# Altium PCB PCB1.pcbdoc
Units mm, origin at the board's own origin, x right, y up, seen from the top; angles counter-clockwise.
Board outline 74 x 38.88 mm, 2 copper layers (Top Layer, Bottom Layer); 38 components, 29 nets, 149 pads, 0 vias.
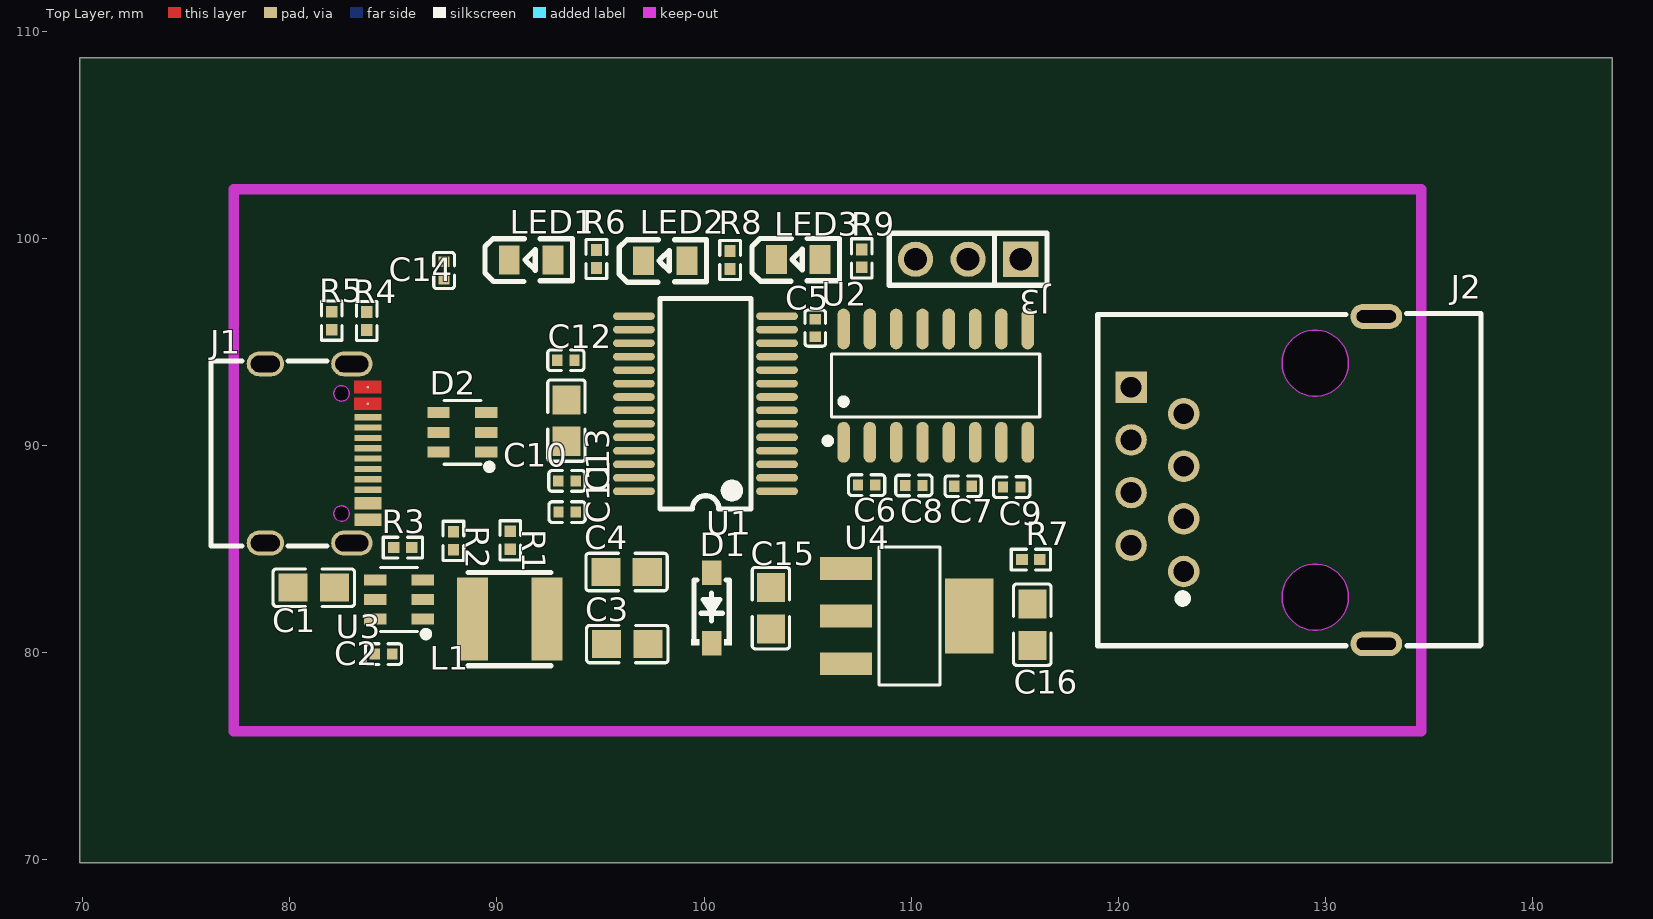
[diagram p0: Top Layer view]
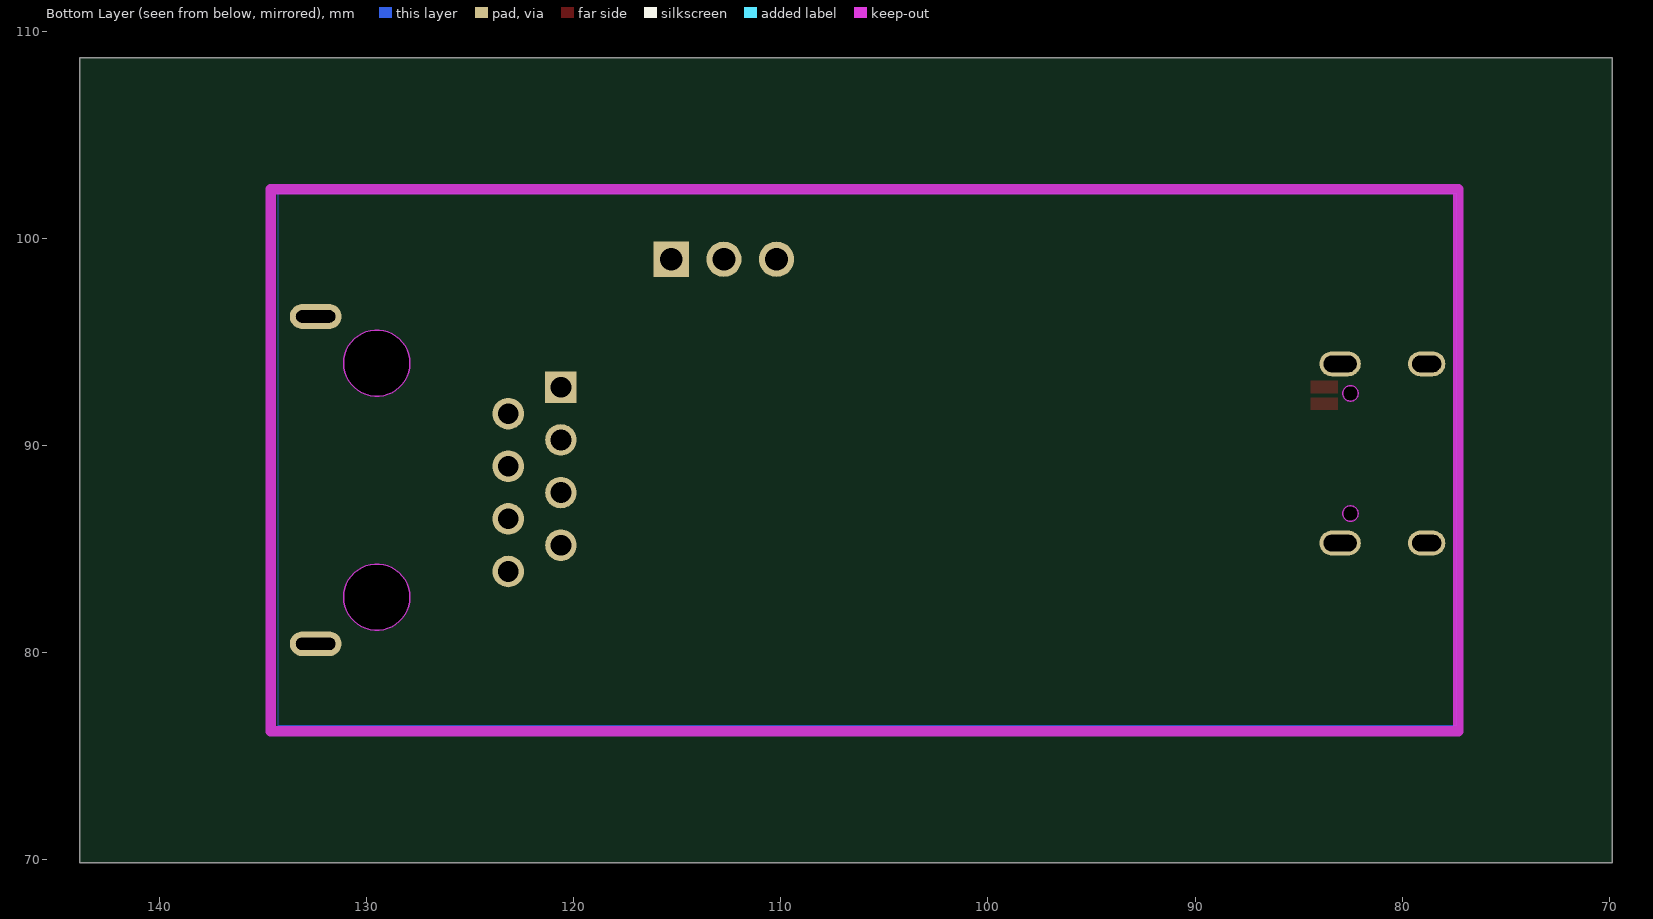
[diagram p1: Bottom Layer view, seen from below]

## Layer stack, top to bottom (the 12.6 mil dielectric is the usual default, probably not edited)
Top Layer: signal copper (thickness not stored)
Dielectric: dielectric 0.32, FR-4, Dk 4.8
Bottom Layer: signal copper (thickness not stored)

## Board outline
143.855,69.85 69.85,69.85 69.85,108.735 143.855,108.735

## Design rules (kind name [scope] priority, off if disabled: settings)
BoardOutlineClearance copperThickness1oz [All] p0: genericclearance=0.254 ignorepadtopadclearanceinfootprint=FALSE except(0: Arc-SplitContinuation Track-SplitContinuation SMDPad-SplitContinuation THPad-SplitContinuation Via-SplitContinuation Fill-SplitContinuation Poly-SplitContinuation Region-SplitContinuation Text-SplitContinuation; 0.152: SMDPad-CutoutEdge THPad-CutoutEdge Via-CutoutEdge Fill-CutoutEdge Region-CutoutEdge; 0.3: Track-OutlineEdge SMDPad-OutlineEdge THPad-OutlineEdge Via-OutlineEdge Fill-OutlineEdge Region-OutlineEdge Poly-OutlineEdge Text-OutlineEdge Track-CutoutEdge)
BoardOutlineClearance copperThickness2oz [All] p0: genericclearance=0.254 ignorepadtopadclearanceinfootprint=FALSE except(0: Arc-SplitContinuation Track-SplitContinuation SMDPad-SplitContinuation THPad-SplitContinuation Via-SplitContinuation Fill-SplitContinuation Poly-SplitContinuation Region-SplitContinuation Text-SplitContinuation; 0.152: SMDPad-CutoutEdge THPad-CutoutEdge Via-CutoutEdge Fill-CutoutEdge Region-CutoutEdge; 0.3: Track-OutlineEdge SMDPad-OutlineEdge THPad-OutlineEdge Via-OutlineEdge Fill-OutlineEdge Region-OutlineEdge Poly-OutlineEdge Text-OutlineEdge Track-CutoutEdge)
Clearance copperThickness1oz [(InNet('GND') OR InNet('VUSB') OR InNet('VBOOST') OR InNet('$1N3108') OR InNet('$1N3104') OR InNet('$1N3119') OR InNet('$1N3114') OR InNet('$1N3125') OR InNet('$1N3129') OR InNet('V12_OUT') OR InNet('UD+') OR InNet('UD-') OR InNet('$1N2860') OR InNet('$1N4089') OR InNet('TXLED') OR InNet('$1N4091') OR InNet('RXLED') OR InNet('$1N4093') OR InNet('$1N2875') OR InNet('$1N2847') OR InNet('$1N3909') OR InNet('$1N3913') OR InNet('$1N3570') OR InNet('RS232_RX') OR InNet('RS232_TX') OR InNet('UART_TX') OR InNet('UART_RX') OR InNet('$1N3345') OR InNet('V3V3'))] p1: gap=0.178 ignorepadtopadclearanceinfootprint=FALSE except(0.102: Track-Track; 0.152: Track-SMDPad SMDPad-SMDPad Track-THPad SMDPad-THPad THPad-THPad Track-Via SMDPad-Via THPad-Via Via-Via Track-Fill SMDPad-Fill THPad-Fill Via-Fill Fill-Fill SMDPad-Region THPad-Region Via-Region Fill-Region Region-Region Track-Poly SMDPad-Poly THPad-Poly Via-Poly Fill-Poly Poly-Poly Track-Text SMDPad-Text THPad-Text Via-Text Fill-Text Region-Text Poly-Text Text-Text; 0.175: Track-Hole SMDPad-Hole THPad-Hole Via-Hole Fill-Hole Region-Hole Poly-Hole Text-Hole Sheet-Hole; 0.3: Track-Region Region-Poly Track-Sheet SMDPad-Sheet THPad-Sheet Via-Sheet Fill-Sheet Region-Sheet Poly-Sheet Text-Sheet)
Clearance copperThickness2oz [All] p1: gap=0.178 ignorepadtopadclearanceinfootprint=FALSE except(0.152: Track-SMDPad SMDPad-SMDPad Track-THPad SMDPad-THPad THPad-THPad Track-Via SMDPad-Via THPad-Via Via-Via Track-Fill SMDPad-Fill THPad-Fill Via-Fill Fill-Fill SMDPad-Region THPad-Region Via-Region Fill-Region Region-Region Track-Poly SMDPad-Poly THPad-Poly Via-Poly Fill-Poly Poly-Poly Track-Text SMDPad-Text THPad-Text Via-Text Fill-Text Region-Text Poly-Text Text-Text; 0.175: Track-Hole SMDPad-Hole THPad-Hole Via-Hole Fill-Hole Region-Hole Poly-Hole Text-Hole Sheet-Hole; 0.203: Track-Track; 0.3: Track-Region Region-Poly Track-Sheet SMDPad-Sheet THPad-Sheet Via-Sheet Fill-Sheet Region-Sheet Poly-Sheet Text-Sheet)
DiffPairsRouting differentialPair [All] p1: maxuncoupledlength=10 minlimit=5.9843 maxlimit=5.9843 mostfreqgap=5.9843 toplayer_minwidth=5 toplayer_prefwidth=10 toplayer_maxwidth=100 bottomlayer_minwidth=5 bottomlayer_prefwidth=10 bottomlayer_maxwidth=100
PasteMaskExpansion pasteMaskExpansion [All] p1: expansion=0
PlaneConnect innerPlane [All] p1: planeconnectstyle=Relief reliefexpansion=0.508 reliefentries=4 reliefconductorwidth=0.254 reliefairgap=0.254
PolygonConnect copperRegion [All] p1: connectstyle=Relief reliefentries=4 reliefconductorwidth=10 polygonreliefangle="90 Angle" airgapwidth=10
RoutingVias viaSize [All] p1: viastyle="Through Hole" holewidth=12.0078 minholewidth=11.811 maxholewidth=248.0314 width=24.0158 minwidth=19.685 maxwidth=393.7008
SolderMaskExpansion solderMaskExpansion [All] p1: useseparateexpansions=TRUE expansion=2.0079 expansionbottom=2.0079
Width copperThickness1oz [All] p1: maxlimit=100 minlimit=5 preferedwidth=10
Width copperThickness2oz [All] p1: maxlimit=100 minlimit=8 preferedwidth=10

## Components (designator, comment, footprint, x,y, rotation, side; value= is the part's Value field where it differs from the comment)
C1 "CL21A226MAQNNNE" C0805 81.161,83.139 r180 top
C2 "CL05B104KB54PNC" C0402 84.527,79.933 r0 top
C3 "CL21A226MAQNNNE" C0805 96.296,80.418 r0 top
C4 "CL21A475KAQNNNE" C0805 96.262,83.896 r0 top
C5 "CL05B104KB54PNC" C0402 105.368,95.672 r270 top
C6 "CL05B104KB54PNC" C0402 107.852,88.094 r0 top
C7 "CL05B104KB54PNC" C0402 112.505,88.04 r0 top
C8 "CL05B104KB54PNC" C0402 110.125,88.075 r0 top
C9 "CL05B104KB54PNC" C0402 114.853,87.994 r0 top
C10 "CL21A475KAQNNNE" C0805 93.356,91.207 r90 top
C11 "CL05B104KB54PNC" C0402 93.391,86.79 r180 top
C12 "CL05B104KB54PNC" C0402 93.327,94.12 r180 top
C13 "CL05B104KB54PNC" C0402 93.379,88.296 r180 top
C14 "CL05B104KB54PNC" C0402 87.45,98.454 r90 top
C15 "CL21A226MAQNNNE" C0805 103.227,82.151 r270 top
C16 "CL21A226MAQNNNE" C0805 115.845,81.355 r90 top
D1 "B5819W SL" SOD-123_L2.7-W1.6-LS3.7-RD-1 100.365,82.16 r90 top
D2 "USBLC6-2SC6_C7519" SOT-23-6_L2.9-W1.6-P0.95-LS2.8-BL 88.333,90.642 r90 top
J1 "TYPE-C-31-M-12" USB-C_SMD-TYPE-C-31-M-12_1 81.294,89.62 r270 top
J2 "KH-RJ45-58-8P8C" RJ45-TH_KH-RJ45-58-8P8C 126.535,88.333 r90 top
J3 "HDR-M_2.54_1x3P" HDR-TH_3P-P2.54-V-M 112.747,98.996 r180 top
L1 "SMNR4020-22UH" IND-SMD_L4.0-W4.0_LQH44PN2R2MP0L 90.615,81.625 r0 top
LED1 "KT-0805G" LED0805-R-RD 91.653,98.969 r0 top
LED2 "KT-0805G" LED0805-R-RD 98.125,98.924 r0 top
LED3 "KT-0805Y" LED0805-R-RD 104.544,98.982 r0 top
R1 "0402WGF1003TCE" R0402 90.646,85.427 r270 top
R2 "0402WGF5101TCE" R0402 87.901,85.403 r90 top
R3 "0402WGF1002TCE" R0402 85.458,85.075 r0 top
R4 "0402WGF5101TCE" R0402 83.719,96.014 r270 top
R5 "0402WGF5101TCE" R0402 82.025,96.032 r270 top
R6 "0402WGF1001TCE" R0402 94.803,99.011 r270 top
R7 "0402WGF100JTCE" R0402 115.777,84.498 r0 top
R8 "0402WGF1001TCE" R0402 101.259,98.958 r90 top
R9 "0402WGF1001TCE" R0402 107.616,99.039 r90 top
U1 "FT232RL-REEL" SSOP-28_L10.2-W5.3-P0.65-LS7.8-BL 100.07,92.021 r90 top
U2 "MAX3232CSE+T_C7258" SOIC-16_L9.9-W3.9-P1.27-LS6.0-BL 111.18,92.895 r0 top
U3 "MT3608" SOT-23-6_L2.9-W1.6-P0.95-LS2.8-BL 85.272,82.568 r90 top
U4 "AMS1117-3.3_C6186" SOT-223-3_L6.5-W3.4-P2.30-LS7.0-BR 109.822,81.773 r180 top

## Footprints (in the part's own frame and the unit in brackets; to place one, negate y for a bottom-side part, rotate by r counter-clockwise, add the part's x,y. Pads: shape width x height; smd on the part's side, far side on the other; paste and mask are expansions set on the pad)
C0402 [mm]
  rect 0.5x0.54 smd: 1(-0.42,0) 2(0.42,0)
  silkscreen extent -0.87,-0.5 0.87,0.5
C0805 [mm]
  rect 1.41x1.35 smd: 1(-1,0) 2(1,0)
  silkscreen extent -1.96,-0.9 1.96,0.9
HDR-TH_3P-P2.54-V-M [mm]
  rect 1.7x1.7 hole 1.1: 1(-2.54,0)
  round 1.7 hole 1.1: 2(0,0) 3(2.54,0)
  silkscreen extent -3.81,-1.25 3.81,1.25
IND-SMD_L4.0-W4.0_LQH44PN2R2MP0L [mm]
  rect 1.5x4 smd: 1(-1.8,0) 2(1.8,0)
  silkscreen extent -2,-2.25 2,2.25
LED0805-R-RD [mm]
  rect 1x1.4 smd: 1(1.05,0) 2(-1.05,0)
  silkscreen extent -2.22,-1.04 1.99,1.01
R0402 [mm]
  rect 0.566x0.54 smd: 1(-0.433,0) 2(0.433,0)
  silkscreen extent -0.94,-0.5 0.94,0.5
RJ45-TH_KH-RJ45-58-8P8C [mil]
  round 60 hole 39.37: 1(-173.61,133.07) 2(-123.62,233.07) 3(-73.61,133.07) 4(-23.61,233.07) 5(26.39,133.07) 6(76.38,233.07) 7(126.39,133.07)
  rect 60x60 hole 39.37: 8(176.39,233.07)
  oval 47.24x98.42 hole 23.62 slot 74.8 at 90 deg: 9(-311.02,-233.07) 10(311.02,-233.07)
  Board Outline Layer circle w0.2: c222.44,-116.93 r62.99
  Board Outline Layer circle w0.2: c-222.44,-116.93 r62.99
  Board Outline Layer region: 222.44,-179.92 195.11,-173.68 173.19,-156.2 161.03,-130.95 161.03,-102.91 173.19,-77.66 195.11,-60.18 222.44,-53.94 222.44,-53.94 249.77,-60.18 271.69,-77.66 283.85,-102.91 283.85,-130.95 271.69,-156.2 249.77,-173.68 222.44,-179.92
  Board Outline Layer region: -222.44,-179.92 -249.77,-173.68 -271.69,-156.2 -283.85,-130.95 -283.85,-102.91 -271.69,-77.66 -249.77,-60.18 -222.44,-53.94 -222.44,-53.94 -195.11,-60.18 -173.19,-77.66 -161.03,-102.91 -161.03,-130.95 -173.19,-156.2 -195.11,-173.68 -222.44,-179.92
  Multi-Layer board cut-out: 222.44,-179.92 195.11,-173.68 173.19,-156.2 161.03,-130.95 161.03,-102.91 173.19,-77.66 195.11,-60.18 222.44,-53.94 222.44,-53.94 249.77,-60.18 271.69,-77.66 283.85,-102.91 283.85,-130.95 271.69,-156.2 249.77,-173.68 222.44,-179.92
  Multi-Layer board cut-out: -222.44,-179.92 -249.77,-173.68 -271.69,-156.2 -283.85,-130.95 -283.85,-102.91 -271.69,-77.66 -249.77,-60.18 -222.44,-53.94 -222.44,-53.94 -195.11,-60.18 -173.19,-77.66 -161.03,-102.91 -161.03,-130.95 -173.19,-156.2 -195.11,-173.68 -222.44,-179.92
  silkscreen extent -315,-432 317,296
SOD-123_L2.7-W1.6-LS3.7-RD-1 [mm]
  rect 1.2x0.95 smd: 1(-1.7,0) 2(1.7,0)
  silkscreen extent -1.81,-0.98 1.35,0.98
SOIC-16_L9.9-W3.9-P1.27-LS6.0-BL [mm]
  oval 0.602x1.971 smd: 1(-4.445,-2.736) 2(-3.175,-2.736) 3(-1.905,-2.736) 4(-0.635,-2.736) 5(0.635,-2.736) 6(1.905,-2.736) 7(3.175,-2.736) 8(4.445,-2.736) 9(4.445,2.736) 10(3.175,2.736) 11(1.905,2.736) 12(0.635,2.736) 13(-0.635,2.736) 14(-1.905,2.736) 15(-3.175,2.736) 16(-4.445,2.736)
  silkscreen extent -5.36,-2.82 5.03,1.52
SOT-23-6_L2.9-W1.6-P0.95-LS2.8-BL [mm]
  rect 0.532x1.072 smd: 1(-0.95,-1.149) 2(0,-1.149) 3(0.95,-1.149) 4(0.95,1.149) 5(0,1.149) 6(-0.95,1.149)
  silkscreen extent -1.82,-1.45 1.54,0.89
SOT-223-3_L6.5-W3.4-P2.30-LS7.0-BR [mm]
  rect 2.5x1.1 smd: 1(2.97,-2.3) 2(2.97,0) 3(2.97,2.3)
  rect 2.34x3.6 smd: 4(-2.97,0)
  silkscreen extent -1.57,-3.33 1.37,3.33
SSOP-28_L10.2-W5.3-P0.65-LS7.8-BL [mm]
  oval 0.364x2.015 smd: 1(-4.225,-3.455) 2(-3.575,-3.455) 3(-2.925,-3.455) 4(-2.275,-3.455) 5(-1.625,-3.455) 6(-0.975,-3.455) 7(-0.325,-3.455) 8(0.325,-3.455) 9(0.975,-3.455) 10(1.625,-3.455) 11(2.275,-3.455) 12(2.925,-3.455) 13(3.575,-3.455) 14(4.225,-3.455) 15(4.225,3.455) 16(3.575,3.455) 17(2.925,3.455) 18(2.275,3.455) 19(1.625,3.455) 20(0.975,3.455) 21(0.325,3.455) 22(-0.325,3.455) 23(-0.975,3.455) 24(-1.625,3.455) 25(-2.275,3.455) 26(-2.925,3.455) 27(-3.575,3.455) 28(-4.225,3.455)
  silkscreen extent -5.08,-2.2 5.08,2.2
USB-C_SMD-TYPE-C-31-M-12_1 [mm]
  oval 1.2x2 hole 0.8 slot 1.6 at 90 deg: 1(4.325,1.706) 4(-4.325,1.706)
  oval 1.2x1.8 hole 0.8 slot 1.4 at 90 deg copper offset 0,0: 2(4.325,-2.474) 3(-4.325,-2.474)
  round 0.12 smd: A1B12(-3.2,2.474) A4B9(-2.4,2.474)
  rect 0.3x1.3 smd: A5(-1.25,2.474) A6(-0.25,2.474) A7(0.25,2.474) A8(1.25,2.474) B5(1.75,2.474) B6(0.75,2.474) B7(-0.75,2.474) B8(-1.75,2.474)
  rect 0.6x1.3 smd: B1A12(3.2,2.474) B4A9(2.4,2.474)
  Top Layer region: -2.9,1.824 -2.9,3.124 -3.2,3.124 -3.2,3.124 -3.5,3.124 -3.5,1.824 -3.2,1.824 -3.2,1.824
  Top Layer region: -2.1,1.824 -2.1,3.124 -2.4,3.124 -2.4,3.124 -2.7,3.124 -2.7,1.824 -2.4,1.824 -2.4,1.824
  Board Outline Layer circle w0.005: c-2.9,1.206 r0.375
  Board Outline Layer circle w0.005: c2.9,1.206 r0.375
  Board Outline Layer region: -2.9,1.581 -2.737,1.543 -2.607,1.439 -2.534,1.289 -2.534,1.122 -2.607,0.972 -2.737,0.868 -2.9,0.831 -2.9,0.831 -3.063,0.868 -3.193,0.972 -3.266,1.122 -3.266,1.289 -3.193,1.439 -3.063,1.543 -2.9,1.581
  Board Outline Layer region: 2.9,1.581 3.063,1.543 3.193,1.439 3.266,1.289 3.266,1.122 3.193,0.972 3.063,0.868 2.9,0.831 2.9,0.831 2.737,0.868 2.607,0.972 2.534,1.122 2.534,1.289 2.607,1.439 2.737,1.543 2.9,1.581
  Multi-Layer board cut-out: -2.9,1.581 -2.737,1.543 -2.607,1.439 -2.534,1.289 -2.534,1.122 -2.607,0.972 -2.737,0.868 -2.9,0.831 -2.9,0.831 -3.063,0.868 -3.193,0.972 -3.266,1.122 -3.266,1.289 -3.193,1.439 -3.063,1.543 -2.9,1.581
  Multi-Layer board cut-out: 2.9,1.581 3.063,1.543 3.193,1.439 3.266,1.289 3.266,1.122 3.193,0.972 3.063,0.868 2.9,0.831 2.9,0.831 2.737,0.868 2.607,0.972 2.534,1.122 2.534,1.289 2.607,1.439 2.737,1.543 2.9,1.581
  silkscreen extent -4.47,-5.09 4.47,0.49

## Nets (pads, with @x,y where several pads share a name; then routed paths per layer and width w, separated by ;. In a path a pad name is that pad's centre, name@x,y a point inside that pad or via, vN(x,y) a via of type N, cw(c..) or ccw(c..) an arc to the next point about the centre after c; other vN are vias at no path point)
$1N2847: R3.1 U3.4
$1N2860: L1.1 U3.1
$1N2875: R1.1 R2.2 U3.3
$1N3104: C6.1 U2.1
$1N3108: C6.2 U2.3
$1N3114: C7.1 U2.4
$1N3119: C7.2 U2.5
$1N3125: C8.1 U2.2
$1N3129: C9.1 U2.6
$1N3345: C12.1 U1.17
$1N3570: J2.3 R7.2
$1N3909: J1.A5 R4.2
$1N3913: J1.B5 R5.2
$1N4089: LED1.1 R6.1
$1N4091: LED2.1 R8.1
$1N4093: LED3.1 R9.1
GND: C1.2 C2.2 C3.2 C4.2 C5.1 C8.2 C9.2 C10.1 C11.1 C12.2 C13.1 C14.2 C15.1 C16.1 D2.2 J1.1 J1.2 J1.3 J1.4 J1.A1B12 J1.B1A12 J2.4 J2.7 J2.8 J2.9 J2.10 J3.3 LED1.2 R2.1 R4.1 R5.1 U1.6 U1.7 U1.9 U1.10 U1.11 U1.18 U1.21 U1.25 U1.26 U2.15 U3.2 U4.1
RS232_RX: J2.5 U2.13
RS232_TX: J2.6 U2.14
RXLED: LED3.2 U1.22
TXLED: LED2.2 U1.23
UART_RX: J3.2 U1.5 U2.12
UART_TX: J3.1 U1.1 U2.11
UD+: D2.1 D2.6 J1.A6 J1.B6 U1.15
UD-: D2.3 D2.4 J1.A7 J1.B7 U1.16
V3V3: C16.2 R7.1 U4.2 U4.4
V12_OUT: D1.1 J2.1 J2.2
VBOOST: C3.1 C4.1 D1.2 L1.2 R1.2
VUSB: C1.1 C2.1 C5.2 C10.2 C11.2 C13.2 C14.1 C15.2 D2.5 J1.A4B9 J1.B4A9 R3.2 R6.2 R8.2 R9.2 U1.4 U1.20 U2.16 U3.5 U4.3
pads on no net: J1.A8 J1.B8 U1.2 U1.3 U1.8 U1.12 U1.13 U1.14 U1.19 U1.24 U1.27 U1.28 U2.7 U2.8 U2.9 U2.10 U3.6

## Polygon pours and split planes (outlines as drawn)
GND on Bottom Layer (solid, remove dead copper, pour order 0): 77.364,102.167 134.281,102.167 134.281,76.507 77.364,76.507

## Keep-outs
Board Outline Layer:
  lines w0.508: 77.294,76.2 134.624,76.2 134.624,102.385 77.294,102.385 77.294,76.2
